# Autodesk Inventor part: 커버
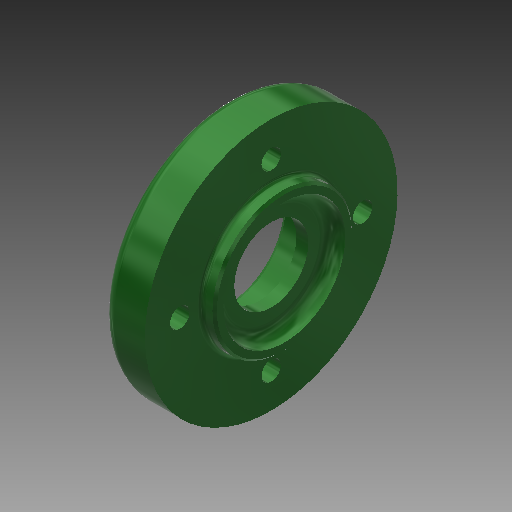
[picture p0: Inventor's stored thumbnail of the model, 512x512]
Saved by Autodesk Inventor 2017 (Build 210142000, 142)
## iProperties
Created: 2015-11
Part Number: 커버
Material: 알루미늄 6061
Document SubType Name: Modeling
Designer: mduedu
Density: 2.71 g/cm^3
Mass: 57.8273 g
Surface Area: 81.1807 cm^2
Volume: 21.3385 cm^3
Appearance: 매끄러움 - 짙은 산림 녹색
Author: mduedu
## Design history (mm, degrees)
sketch "스케치1"
  geometry: L1 (-6.5, 0)-(6.5, 0); L2 (-6.5, 0)-(-6.5, 29); L3 (-6.5, 29)-(3.5, 29); L4 (3.5, 29)-(3.5, 16); L5 (3.5, 16)-(6.5, 16); L6 (6.5, 16)-(6.5, 0); 2 further points
  constraints: 12 end point, 3 perpendicular, 2 parallel, 1 coincident, 1 horizontal, 1 midpoint
  dimensions: "d0" = 13 distance of L1.start L1.end; "d1" = 58 diameter of L3 L1; "d2" = 3 distance of L4.end L5.end; "d3" = 32 diameter of L5 L1
revolve "회전1" sketch "스케치1" stored, may be unused: angle "d4" = 90 deg
hole "구멍1" diameter "d7" = 28; stored, may be unused: countersink angle "d11" = 90 deg, drill point angle "d13" = 0 deg; dims "d8" = 6, "d9" = 4, "d10" = 2, "d12" = 3, "d65" = 10, "d66" = 10
hole "구멍2" diameter "d16" = 25; stored, may be unused: countersink angle "d20" = 90 deg, drill point angle "d22" = 0 deg; dims "d17" = 6, "d18" = 4, "d19" = 2, "d21" = 7.3, "d67" = 10, "d68" = 10
hole "구멍3" diameter "d25" = 17; stored, may be unused: countersink angle "d29" = 90 deg, drill point angle "d31" = 0 deg; dims "d23" = 10, "d24" = 10, "d26" = 6, "d27" = 4, "d28" = 2, "d30" = 4.2
chamfer "모따기1" distance "d32" = 0.7; stored, may be unused: second distance "d33" = 2, angle "d34" = 30 deg
fillet "모깎기1" dims "d35" = 0.2
fillet "모깎기2" dims "d36" = 3
fillet "모깎기3" dims "d37" = 3
fillet "모깎기4" dims "d38" = 1
sketch "스케치3" dims "d61" = 42
  geometry: C1 r 29 at (0, 0) reference; 2 further points
  constraints: 2 vertical alignment, 1 coincident, 2 other
hole "구멍4" sketch "스케치3" at (0, -21) diameter "d44" = 4.5; stored, may be unused: countersink angle "d48" = 90 deg, drill point angle "d50" = 0 deg; dims "d45" = 6, "d46" = 8, "d47" = 4.6, "d49" = 8
chamfer "모따기2" distance "d62" = 0.5; stored, may be unused: second distance "d63" = 2, angle "d64" = 45 deg
node "솔리드1"
pattern_circular "원형 패턴1" dims angle "d54" = 360 deg
